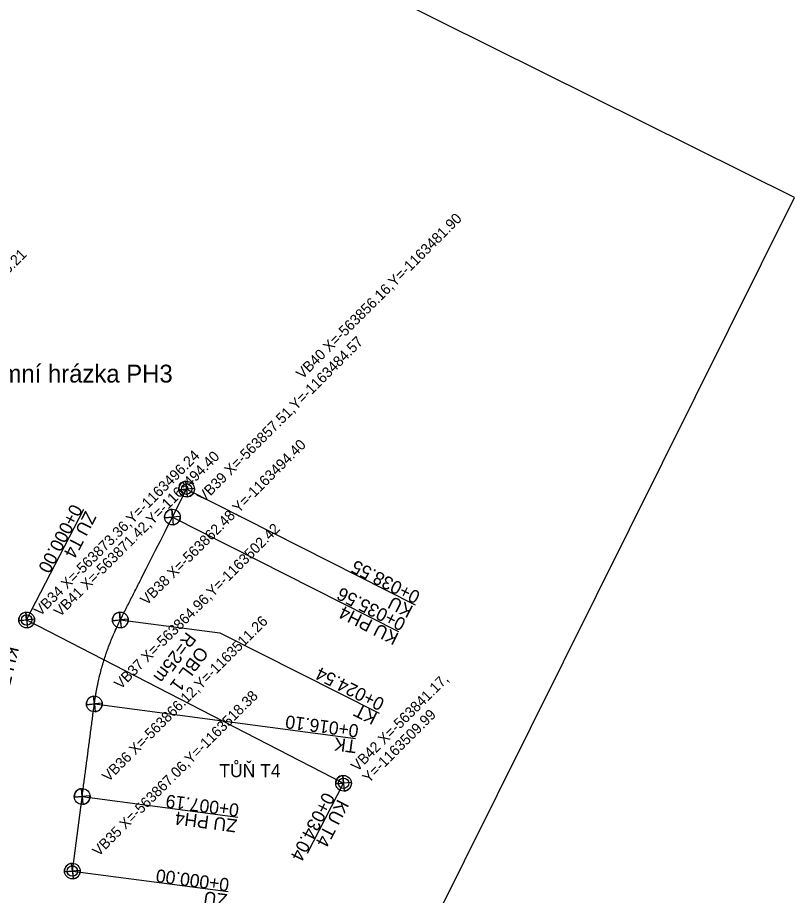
# Model space of a CAD drawing. Extents: x -564052 to -563798, y -1163587 to -1163361.
# Drawn here: x -563872.3 to -563798.1, y -1163520.7 to -1163436.9 of the extents above; entities that cross this region are included whole.
import ezdxf

# ---------------------------------------------------------------- set-up
doc = ezdxf.new("R2010")
doc.units = 0
for name, color, linetype in [('4', 7, 'Continuous'), ('5', 7, 'Continuous'), ('_popis staničení PH4', 7, 'Continuous'), ('_popis staničení T3', 7, 'Continuous'), ('_popis staničení T4', 7, 'Continuous'), ('_rám C35', 7, 'Continuous'), ('_rám PH2 a PH4', 7, 'Continuous'), ('Default', 7, 'Continuous')]:
    doc.layers.add(name, color=color, linetype=linetype)

msp = doc.modelspace()

# ---------------------------------------------------------------- linework, layer by layer
msp.add_lwpolyline([(-563867.063, -1163518.388), (-563867.062, -1163518.383), (-563866.103, -1163511.1), (-563866.083, -1163510.947), (-563866.062, -1163510.793), (-563866.042, -1163510.64), (-563866.022, -1163510.486), (-563866.017, -1163510.452), (-563866.002, -1163510.332), (-563865.982, -1163510.179), (-563865.961, -1163510.025), (-563865.941, -1163509.872), (-563865.921, -1163509.718), (-563865.901, -1163509.565), (-563865.887, -1163509.46), (-563865.88, -1163509.411), (-563865.86, -1163509.258), (-563865.84, -1163509.104), (-563865.82, -1163508.951), (-563865.8, -1163508.797), (-563865.779, -1163508.644), (-563865.759, -1163508.49), (-563865.756, -1163508.469), (-563865.739, -1163508.337), (-563865.719, -1163508.183), (-563865.698, -1163508.029), (-563865.678, -1163507.876), (-563865.658, -1163507.722), (-563865.638, -1163507.569), (-563865.626, -1163507.477), (-563865.618, -1163507.415), (-563865.597, -1163507.262), (-563865.577, -1163507.108), (-563865.557, -1163506.955), (-563865.537, -1163506.801), (-563865.517, -1163506.648), (-563865.496, -1163506.494), (-563865.495, -1163506.486), (-563865.476, -1163506.341), (-563865.456, -1163506.187), (-563865.436, -1163506.034), (-563865.415, -1163505.88), (-563865.395, -1163505.726), (-563865.375, -1163505.573), (-563865.365, -1163505.494), (-563865.355, -1163505.419), (-563865.335, -1163505.266), (-563865.314, -1163505.112), (-563865.294, -1163504.959), (-563865.274, -1163504.805), (-563865.254, -1163504.652), (-563865.234, -1163504.503), (-563865.233, -1163504.498), (-563865.213, -1163504.345), (-563865.193, -1163504.191), (-563865.173, -1163504.038), (-563865.153, -1163503.884), (-563865.132, -1163503.731), (-563865.112, -1163503.577), (-563865.104, -1163503.512), (-563865.092, -1163503.424), (-563865.072, -1163503.27), (-563865.052, -1163503.116), (-563865.031, -1163502.963), (-563865.011, -1163502.809), (-563864.991, -1163502.656), (-563864.973, -1163502.52), (-563864.971, -1163502.502), (-563864.96, -1163502.42), (-563864.95, -1163502.349), (-563864.929, -1163502.195), (-563864.907, -1163502.042), (-563864.884, -1163501.889), (-563864.86, -1163501.736), (-563864.835, -1163501.583), (-563864.826, -1163501.531), (-563864.809, -1163501.43), (-563864.8, -1163501.378), (-563864.782, -1163501.278), (-563864.755, -1163501.126), (-563864.726, -1163500.973), (-563864.696, -1163500.821), (-563864.666, -1163500.67), (-563864.641, -1163500.548), (-563864.634, -1163500.518), (-563864.602, -1163500.367), (-563864.597, -1163500.343), (-563864.568, -1163500.215), (-563864.534, -1163500.064), (-563864.499, -1163499.914), (-563864.462, -1163499.763), (-563864.425, -1163499.613), (-563864.416, -1163499.574), (-563864.387, -1163499.463), (-563864.35, -1163499.318), (-563864.348, -1163499.313), (-563864.308, -1163499.163), (-563864.267, -1163499.014), (-563864.226, -1163498.865), (-563864.183, -1163498.716), (-563864.152, -1163498.61), (-563864.139, -1163498.567), (-563864.095, -1163498.419), (-563864.06, -1163498.304), (-563864.049, -1163498.271), (-563864.003, -1163498.123), (-563863.956, -1163497.976), (-563863.908, -1163497.829), (-563863.858, -1163497.682), (-563863.85, -1163497.656), (-563863.808, -1163497.535), (-563863.757, -1163497.389), (-563863.727, -1163497.303), (-563863.706, -1163497.243), (-563863.653, -1163497.097), (-563863.599, -1163496.952), (-563863.545, -1163496.807), (-563863.51, -1163496.716), (-563863.489, -1163496.663), (-563863.433, -1163496.518), (-563863.376, -1163496.374), (-563863.353, -1163496.317), (-563863.318, -1163496.231), (-563863.259, -1163496.088), (-563863.199, -1163495.945), (-563863.138, -1163495.802), (-563863.133, -1163495.79), (-563863.076, -1163495.66), (-563863.014, -1163495.519), (-563862.95, -1163495.377), (-563862.937, -1163495.348), (-563862.886, -1163495.237), (-563862.821, -1163495.096), (-563862.755, -1163494.956), (-563862.719, -1163494.88), (-563862.688, -1163494.816), (-563862.62, -1163494.677), (-563862.552, -1163494.538), (-563862.482, -1163494.4), (-563862.481, -1163494.397), (-563862.412, -1163494.262), (-563862.342, -1163494.123), (-563862.272, -1163493.985), (-563862.202, -1163493.847), (-563862.133, -1163493.709), (-563862.063, -1163493.571), (-563861.993, -1163493.433), (-563861.923, -1163493.294), (-563861.853, -1163493.156), (-563861.821, -1163493.093), (-563861.783, -1163493.018), (-563861.713, -1163492.88), (-563861.643, -1163492.742), (-563861.573, -1163492.604), (-563861.503, -1163492.465), (-563861.433, -1163492.327), (-563861.369, -1163492.2), (-563861.364, -1163492.189), (-563861.294, -1163492.051), (-563861.224, -1163491.913), (-563861.154, -1163491.774), (-563861.084, -1163491.636), (-563861.014, -1163491.498), (-563860.944, -1163491.36), (-563860.918, -1163491.308), (-563860.874, -1163491.222), (-563860.804, -1163491.084), (-563860.734, -1163490.945), (-563860.664, -1163490.807), (-563860.594, -1163490.669), (-563860.525, -1163490.531), (-563860.522, -1163490.527), (-563860.466, -1163490.416), (-563860.387, -1163490.259), (-563860.015, -1163489.524), (-563859.563, -1163488.631), (-563859.112, -1163487.739), (-563858.66, -1163486.847), (-563858.209, -1163485.954), (-563858.129, -1163485.798), (-563857.757, -1163485.062), (-563856.157, -1163481.899)])
at = {"layer": '5'}
msp.add_line((-563871.424, -1163494.398), (-563841.172, -1163509.993), dxfattribs=at)
at = {"layer": '_popis staničení PH4'}
for points in [[(-563856.157, -1163481.899), (-563834.335, -1163492.941)], [(-563857.507, -1163484.567), (-563835.922, -1163495.489)], [(-563862.481, -1163494.397), (-563852.983, -1163495.62), (-563837.783, -1163503.311)], [(-563864.96, -1163502.42), (-563840.022, -1163505.704)], [(-563866.124, -1163511.258), (-563851.252, -1163513.217)], [(-563867.062, -1163518.383), (-563852.19, -1163520.341)]]:
    msp.add_lwpolyline(points, dxfattribs=at)
for centre in [(-563856.157, -1163481.899), (-563867.062, -1163518.383)]:
    msp.add_circle(centre, 0.5, dxfattribs=at)
at = {"layer": '_popis staničení T4'}
for points in [[(-563871.424, -1163494.398), (-563865.967, -1163483.812)], [(-563844.608, -1163516.659), (-563841.172, -1163509.993)]]:
    msp.add_lwpolyline(points, dxfattribs=at)
for centre in [(-563871.424, -1163494.398), (-563841.172, -1163509.993)]:
    msp.add_circle(centre, 0.5, dxfattribs=at)
at = {"layer": '_rám C35'}
for p, q in [((-563855.41, -1163481.83), (-563856.904, -1163481.969)), ((-563856.904, -1163481.969), (-563856.157, -1163481.899)), ((-563856.904, -1163481.969), (-563856.157, -1163481.899)), ((-563856.226, -1163481.152), (-563856.087, -1163482.646)), ((-563856.157, -1163481.899), (-563856.226, -1163481.152)), ((-563856.157, -1163481.899), (-563856.226, -1163481.152)), ((-563855.41, -1163481.83), (-563856.157, -1163481.899)), ((-563856.157, -1163481.899), (-563856.087, -1163482.646)), ((-563856.76, -1163484.498), (-563858.254, -1163484.637)), ((-563857.576, -1163483.82), (-563857.437, -1163485.314)), ((-563857.507, -1163484.567), (-563857.576, -1163483.82)), ((-563857.507, -1163484.567), (-563857.576, -1163483.82)), ((-563856.76, -1163484.498), (-563857.507, -1163484.567)), ((-563858.254, -1163484.637), (-563857.507, -1163484.567)), ((-563858.254, -1163484.637), (-563857.507, -1163484.567)), ((-563857.507, -1163484.567), (-563857.437, -1163485.314)), ((-563871.424, -1163494.398), (-563871.494, -1163493.65)), ((-563871.424, -1163494.398), (-563871.494, -1163493.65)), ((-563871.494, -1163493.651), (-563871.355, -1163495.144)), ((-563862.55, -1163493.65), (-563862.411, -1163495.144)), ((-563862.481, -1163494.397), (-563862.55, -1163493.65)), ((-563862.481, -1163494.397), (-563862.55, -1163493.65)), ((-563870.677, -1163494.328), (-563872.171, -1163494.467)), ((-563872.171, -1163494.467), (-563871.424, -1163494.398)), ((-563872.171, -1163494.467), (-563871.424, -1163494.398)), ((-563870.677, -1163494.328), (-563871.424, -1163494.398)), ((-563871.424, -1163494.398), (-563871.355, -1163495.145)), ((-563863.228, -1163494.467), (-563862.481, -1163494.397)), ((-563863.228, -1163494.467), (-563862.481, -1163494.397)), ((-563861.734, -1163494.328), (-563863.227, -1163494.467)), ((-563861.734, -1163494.328), (-563862.481, -1163494.397)), ((-563862.481, -1163494.397), (-563862.411, -1163495.144)), ((-563864.96, -1163502.42), (-563865.029, -1163501.673)), ((-563864.96, -1163502.42), (-563865.029, -1163501.673)), ((-563865.029, -1163501.674), (-563864.89, -1163503.167)), ((-563864.213, -1163502.351), (-563865.707, -1163502.49)), ((-563865.707, -1163502.49), (-563864.96, -1163502.42)), ((-563865.707, -1163502.49), (-563864.96, -1163502.42)), ((-563864.213, -1163502.351), (-563864.96, -1163502.42)), ((-563864.96, -1163502.42), (-563864.89, -1163503.167)), ((-563841.172, -1163509.993), (-563841.241, -1163509.245)), ((-563841.172, -1163509.993), (-563841.241, -1163509.245)), ((-563841.241, -1163509.246), (-563841.102, -1163510.739)), ((-563841.919, -1163510.062), (-563841.172, -1163509.993)), ((-563841.919, -1163510.062), (-563841.172, -1163509.993)), ((-563840.425, -1163509.923), (-563841.918, -1163510.062)), ((-563840.425, -1163509.923), (-563841.172, -1163509.993)), ((-563841.172, -1163509.993), (-563841.102, -1163510.74)), ((-563866.871, -1163511.328), (-563866.124, -1163511.258)), ((-563866.871, -1163511.328), (-563866.124, -1163511.258)), ((-563865.377, -1163511.189), (-563866.87, -1163511.328)), ((-563866.124, -1163511.258), (-563866.193, -1163510.511)), ((-563866.124, -1163511.258), (-563866.193, -1163510.511)), ((-563866.193, -1163510.512), (-563866.054, -1163512.005)), ((-563865.377, -1163511.189), (-563866.124, -1163511.258)), ((-563866.124, -1163511.258), (-563866.054, -1163512.006)), ((-563867.131, -1163517.636), (-563866.992, -1163519.13)), ((-563867.062, -1163518.383), (-563867.131, -1163517.636)), ((-563867.062, -1163518.383), (-563867.131, -1163517.636)), ((-563866.315, -1163518.314), (-563867.809, -1163518.453)), ((-563867.809, -1163518.453), (-563867.062, -1163518.383)), ((-563867.809, -1163518.453), (-563867.062, -1163518.383)), ((-563866.315, -1163518.314), (-563867.062, -1163518.383)), ((-563867.062, -1163518.383), (-563866.992, -1163519.13))]:
    msp.add_line(p, q, dxfattribs=at)
for centre in [(-563856.157, -1163481.899), (-563857.507, -1163484.567), (-563871.424, -1163494.398), (-563862.481, -1163494.397), (-563864.96, -1163502.42), (-563841.172, -1163509.993), (-563866.124, -1163511.258), (-563867.062, -1163518.383)]:
    msp.add_circle(centre, 0.75, dxfattribs=at)
for centre, start, end in [((-563856.157, -1163481.899), 95.31679, 185.31679), ((-563856.157, -1163481.899), 95.31679, 185.31679), ((-563856.157, -1163481.899), 275.31679, 5.31679), ((-563857.507, -1163484.567), 95.31679, 185.31679), ((-563857.507, -1163484.567), 95.31679, 185.31679), ((-563857.507, -1163484.567), 275.31679, 5.31679), ((-563871.424, -1163494.398), 95.31679, 185.31679), ((-563871.424, -1163494.398), 95.31679, 185.31679), ((-563862.481, -1163494.397), 95.31679, 185.31679), ((-563862.481, -1163494.397), 95.31679, 185.31679), ((-563871.424, -1163494.398), 275.31679, 5.31679), ((-563862.481, -1163494.397), 275.31679, 5.31679), ((-563864.96, -1163502.42), 95.31679, 185.31679), ((-563864.96, -1163502.42), 95.31679, 185.31679), ((-563864.96, -1163502.42), 275.31679, 5.31679), ((-563841.172, -1163509.993), 95.31679, 185.31679), ((-563841.172, -1163509.993), 95.31679, 185.31679), ((-563841.172, -1163509.993), 275.31679, 5.31679), ((-563866.124, -1163511.258), 95.31679, 185.31679), ((-563866.124, -1163511.258), 95.31679, 185.31679), ((-563866.124, -1163511.258), 275.31679, 5.31679), ((-563867.062, -1163518.383), 95.31679, 185.31679), ((-563867.062, -1163518.383), 95.31679, 185.31679), ((-563867.062, -1163518.383), 275.31679, 5.31679)]:
    msp.add_arc(centre, 0.75, start, end, dxfattribs=at)
at = {"layer": '_rám PH2 a PH4'}
msp.add_lwpolyline([(-564052.283, -1163493.529), (-563864.244, -1163587.024), (-563798.13, -1163454.054), (-563986.169, -1163360.559)], close=True, dxfattribs=at)

# ---------------------------------------------------------------- texts
at = {"layer": '4'}
for s, height, p in [('Zemní hrázka PH3', 1.70472, (-563876.485, -1163471.716)), ('TŮŇ T4', 1.25, (-563853.032, -1163509.412))]:
    msp.add_text(s, height=height, rotation=360, dxfattribs=at).set_placement(p)
at = {"layer": '_popis staničení PH4'}
for s, rotation, p in [('0+038.55', 153.16098, (-563833.751, -1163491.792)), ('0+035.56', 153.16098, (-563835.121, -1163494.388)), ('KU ', 153.16098, (-563834.429, -1163493.131)), ('KU PH4 ', 153.16098, (-563835.799, -1163495.727)), ('R=25m ', 233.41803, (-563856.149, -1163495.465)), ('OBL 1', 233.41803, (-563854.982, -1163496.829)), ('0+024.54', 153.16098, (-563837.159, -1163502.009)), ('KT ', 153.16098, (-563837.836, -1163503.347)), ('0+016.10', 172.4983, (-563839.672, -1163504.406)), ('TK ', 172.4983, (-563839.868, -1163505.893)), ('0+007.19', 172.4983, (-563851.089, -1163511.977)), ('ZU PH4 ', 172.4983, (-563851.285, -1163513.465)), ('0+000.00', 172.4983, (-563852.027, -1163519.102)), ('ZU ', 172.4983, (-563852.223, -1163520.589))]:
    msp.add_text(s, height=1.25, rotation=rotation, dxfattribs=at).set_placement(p)
at = {"layer": '_popis staničení T3'}
msp.add_text('KU T3 ', height=1.25, rotation=256.44325, dxfattribs=at).set_placement((-563873.356, -1163496.804))
at = {"layer": '_popis staničení T4'}
for s, p in [('0+000.00', (-563867.145, -1163483.232)), ('ZU T4 ', (-563865.812, -1163483.919)), ('0+034.04', (-563843.05, -1163510.76)), ('KU T4 ', (-563841.716, -1163511.447))]:
    msp.add_text(s, height=1.25, rotation=242.72906, dxfattribs=at).set_placement(p)
at = {"layer": '_rám C35'}
msp.add_text('osa zemní hrázky, tůně, odpadního příkopu, odpadního průlehu', height=1.25, rotation=333.56303, dxfattribs=at).set_placement((-563908.317, -1163519.191))
at = {"layer": 'Default'}
for s, p in [('VB40 X=-563856.16,Y=-1163481.90', (-563845.102, -1163471.443)), ('VB32 X=-563889.15,Y=-1163476.21', (-563886.652, -1163474.862)), ('VB39 X=-563857.51,Y=-1163484.57', (-563854.519, -1163483.219)), ('VB38 X=-563862.48,Y=-1163494.40', (-563859.981, -1163493.049)), ('VB34 X=-563873.36,Y=-1163496.24', (-563870.133, -1163494.09)), ('VB41 X=-563871.42,Y=-1163494.40', (-563868.236, -1163494.167)), ('VB37 X=-563864.96,Y=-1163502.42', (-563862.46, -1163501.072)), ('VB36 X=-563866.12,Y=-1163511.26', (-563863.624, -1163509.91)), ('VB42 X=-563841.17,', (-563839.858, -1163508.931)), ('VB35 X=-563867.06,Y=-1163518.38', (-563864.562, -1163517.035)), ('Y=-1163509.99', (-563838.762, -1163510.027))]:
    msp.add_text(s, height=1, rotation=45, dxfattribs=at).set_placement(p)

doc.saveas('drawing.dxf')
